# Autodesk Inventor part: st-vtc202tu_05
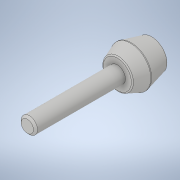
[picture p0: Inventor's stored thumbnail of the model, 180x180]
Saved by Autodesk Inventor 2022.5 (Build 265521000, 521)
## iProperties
Created: 2021-08
Part Number: st-vtc202tu_05
Material: 一般
Document SubType Name: Modeling
Designer: ImaoCorp
Density: 1 g/cm^3
Appearance: 既定
Author: ImaoCorp
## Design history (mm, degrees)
feature "st-vtc202tu_05"
node "ソリッド1"
